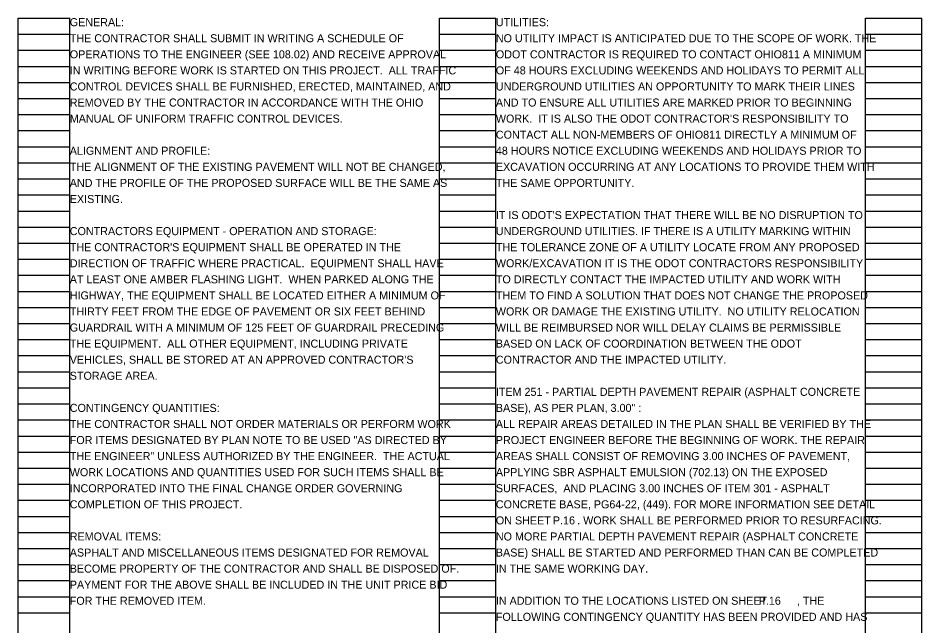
# Model space of a CAD drawing. Extents: x 28776.5 to 28808.5, y 9178.8 to 9230.7.
# Drawn here: x 28778.03 to 28793.77, y 9220.15 to 9230.74 of the extents above; entities that cross this region are included whole.
import ezdxf

# ---------------------------------------------------------------- set-up
doc = ezdxf.new("R2010")
doc.units = 0
doc.layers.add('SH_Data', color=7, linetype='Continuous')
doc.layers.add('SH_Text', color=7, linetype='Continuous')

msp = doc.modelspace()

# ---------------------------------------------------------------- linework, layer by layer
at = {"layer": 'SH_Data'}
for p, q in [((28778.029, 9210.582), (28778.029, 9230.742)), ((28778.029, 9230.742), (28778.929, 9230.742)), ((28778.929, 9210.582), (28778.929, 9230.742)), ((28785.369, 9210.582), (28785.369, 9230.742)), ((28785.369, 9230.742), (28786.349, 9230.742)), ((28786.349, 9210.582), (28786.349, 9230.742)), ((28792.789, 9210.582), (28792.789, 9230.742)), ((28792.789, 9230.742), (28793.769, 9230.742)), ((28793.769, 9210.582), (28793.769, 9230.742)), ((28778.029, 9230.462), (28778.929, 9230.462)), ((28785.369, 9230.462), (28786.349, 9230.462)), ((28792.789, 9230.462), (28793.769, 9230.462)), ((28778.029, 9230.182), (28778.929, 9230.182)), ((28785.369, 9230.182), (28786.349, 9230.182)), ((28792.789, 9230.182), (28793.769, 9230.182)), ((28778.029, 9229.902), (28778.929, 9229.902)), ((28785.369, 9229.902), (28786.349, 9229.902)), ((28792.789, 9229.902), (28793.769, 9229.902)), ((28778.029, 9229.622), (28778.929, 9229.622)), ((28785.369, 9229.622), (28786.349, 9229.622)), ((28792.789, 9229.622), (28793.769, 9229.622)), ((28778.029, 9229.342), (28778.929, 9229.342)), ((28785.369, 9229.342), (28786.349, 9229.342)), ((28792.789, 9229.342), (28793.769, 9229.342)), ((28778.029, 9229.062), (28778.929, 9229.062)), ((28785.369, 9229.062), (28786.349, 9229.062)), ((28792.789, 9229.062), (28793.769, 9229.062)), ((28778.029, 9228.782), (28778.929, 9228.782)), ((28785.369, 9228.782), (28786.349, 9228.782)), ((28792.789, 9228.782), (28793.769, 9228.782)), ((28778.029, 9228.502), (28778.929, 9228.502)), ((28785.369, 9228.502), (28786.349, 9228.502)), ((28792.789, 9228.502), (28793.769, 9228.502)), ((28778.029, 9228.222), (28778.929, 9228.222)), ((28785.369, 9228.222), (28786.349, 9228.222)), ((28792.789, 9228.222), (28793.769, 9228.222)), ((28778.029, 9227.942), (28778.929, 9227.942)), ((28785.369, 9227.942), (28786.349, 9227.942)), ((28792.789, 9227.942), (28793.769, 9227.942)), ((28778.029, 9227.662), (28778.929, 9227.662)), ((28785.369, 9227.662), (28786.349, 9227.662)), ((28792.789, 9227.662), (28793.769, 9227.662)), ((28778.029, 9227.382), (28778.929, 9227.382)), ((28785.369, 9227.382), (28786.349, 9227.382)), ((28792.789, 9227.382), (28793.769, 9227.382)), ((28778.029, 9227.102), (28778.929, 9227.102)), ((28785.369, 9227.102), (28786.349, 9227.102)), ((28792.789, 9227.102), (28793.769, 9227.102)), ((28778.029, 9226.822), (28778.929, 9226.822)), ((28785.369, 9226.822), (28786.349, 9226.822)), ((28792.789, 9226.822), (28793.769, 9226.822)), ((28778.029, 9226.542), (28778.929, 9226.542)), ((28785.369, 9226.542), (28786.349, 9226.542)), ((28792.789, 9226.542), (28793.769, 9226.542)), ((28778.029, 9226.262), (28778.929, 9226.262)), ((28785.369, 9226.262), (28786.349, 9226.262)), ((28792.789, 9226.262), (28793.769, 9226.262)), ((28778.029, 9225.982), (28778.929, 9225.982)), ((28785.369, 9225.982), (28786.349, 9225.982)), ((28792.789, 9225.982), (28793.769, 9225.982)), ((28778.029, 9225.702), (28778.929, 9225.702)), ((28785.369, 9225.702), (28786.349, 9225.702)), ((28792.789, 9225.702), (28793.769, 9225.702)), ((28778.029, 9225.422), (28778.929, 9225.422)), ((28785.369, 9225.422), (28786.349, 9225.422)), ((28792.789, 9225.422), (28793.769, 9225.422)), ((28778.029, 9225.142), (28778.929, 9225.142)), ((28785.369, 9225.142), (28786.349, 9225.142)), ((28792.789, 9225.142), (28793.769, 9225.142)), ((28778.029, 9224.862), (28778.929, 9224.862)), ((28785.369, 9224.862), (28786.349, 9224.862)), ((28792.789, 9224.862), (28793.769, 9224.862)), ((28778.029, 9224.582), (28778.929, 9224.582)), ((28785.369, 9224.582), (28786.349, 9224.582)), ((28792.789, 9224.582), (28793.769, 9224.582)), ((28778.029, 9224.302), (28778.929, 9224.302)), ((28785.369, 9224.302), (28786.349, 9224.302)), ((28792.789, 9224.302), (28793.769, 9224.302)), ((28778.029, 9224.022), (28778.929, 9224.022)), ((28785.369, 9224.022), (28786.349, 9224.022)), ((28792.789, 9224.022), (28793.769, 9224.022)), ((28778.029, 9223.742), (28778.929, 9223.742)), ((28785.369, 9223.742), (28786.349, 9223.742)), ((28792.789, 9223.742), (28793.769, 9223.742)), ((28778.029, 9223.462), (28778.929, 9223.462)), ((28785.369, 9223.462), (28786.349, 9223.462)), ((28792.789, 9223.462), (28793.769, 9223.462)), ((28778.029, 9223.182), (28778.929, 9223.182)), ((28785.369, 9223.182), (28786.349, 9223.182)), ((28792.789, 9223.182), (28793.769, 9223.182)), ((28778.029, 9222.902), (28778.929, 9222.902)), ((28785.369, 9222.902), (28786.349, 9222.902)), ((28792.789, 9222.902), (28793.769, 9222.902)), ((28778.029, 9222.622), (28778.929, 9222.622)), ((28785.369, 9222.622), (28786.349, 9222.622)), ((28792.789, 9222.622), (28793.769, 9222.622)), ((28778.029, 9222.342), (28778.929, 9222.342)), ((28785.369, 9222.342), (28786.349, 9222.342)), ((28792.789, 9222.342), (28793.769, 9222.342)), ((28778.029, 9222.062), (28778.929, 9222.062)), ((28785.369, 9222.062), (28786.349, 9222.062)), ((28792.789, 9222.062), (28793.769, 9222.062)), ((28778.029, 9221.782), (28778.929, 9221.782)), ((28785.369, 9221.782), (28786.349, 9221.782)), ((28792.789, 9221.782), (28793.769, 9221.782)), ((28778.029, 9221.502), (28778.929, 9221.502)), ((28785.369, 9221.502), (28786.349, 9221.502)), ((28792.789, 9221.502), (28793.769, 9221.502)), ((28778.029, 9221.222), (28778.929, 9221.222)), ((28785.369, 9221.222), (28786.349, 9221.222)), ((28792.789, 9221.222), (28793.769, 9221.222)), ((28778.029, 9220.942), (28778.929, 9220.942)), ((28785.369, 9220.942), (28786.349, 9220.942)), ((28792.789, 9220.942), (28793.769, 9220.942)), ((28778.029, 9220.662), (28778.929, 9220.662)), ((28785.369, 9220.662), (28786.349, 9220.662)), ((28792.789, 9220.662), (28793.769, 9220.662)), ((28778.029, 9220.382), (28778.929, 9220.382)), ((28785.369, 9220.382), (28786.349, 9220.382)), ((28792.789, 9220.382), (28793.769, 9220.382))]:
    msp.add_line(p, q, dxfattribs=at)

# ---------------------------------------------------------------- texts
at = {"layer": 'SH_Text'}
for s, p in [('GENERAL:', (28778.929, 9230.602)), ('UTILITIES:', (28786.349, 9230.602)), ('THE CONTRACTOR SHALL SUBMIT IN WRITING A SCHEDULE OF ', (28778.929, 9230.322)), ('NO UTILITY IMPACT IS ANTICIPATED DUE TO THE SCOPE OF WORK. THE ', (28786.349, 9230.322)), ('OPERATIONS TO THE ENGINEER (SEE 108.02) AND RECEIVE APPROVAL ', (28778.929, 9230.042)), ('ODOT CONTRACTOR IS REQUIRED TO CONTACT OHIO811 A MINIMUM ', (28786.349, 9230.042)), ('IN WRITING BEFORE WORK IS STARTED ON THIS PROJECT.  ALL TRAFFIC ', (28778.929, 9229.762)), ('OF 48 HOURS EXCLUDING WEEKENDS AND HOLIDAYS TO PERMIT ALL ', (28786.349, 9229.762)), ('CONTROL DEVICES SHALL BE FURNISHED, ERECTED, MAINTAINED, AND ', (28778.929, 9229.482)), ('UNDERGROUND UTILITIES AN OPPORTUNITY TO MARK THEIR LINES ', (28786.349, 9229.482)), ('REMOVED BY THE CONTRACTOR IN ACCORDANCE WITH THE OHIO ', (28778.929, 9229.202)), ('AND TO ENSURE ALL UTILITIES ARE MARKED PRIOR TO BEGINNING ', (28786.349, 9229.202)), ('MANUAL OF UNIFORM TRAFFIC CONTROL DEVICES.', (28778.929, 9228.922)), ("WORK.  IT IS ALSO THE ODOT CONTRACTOR'S RESPONSIBILITY TO ", (28786.349, 9228.922)), ('CONTACT ALL NON-MEMBERS OF OHIO811 DIRECTLY A MINIMUM OF ', (28786.349, 9228.642)), ('ALIGNMENT AND PROFILE:', (28778.929, 9228.362)), ('48 HOURS NOTICE EXCLUDING WEEKENDS AND HOLIDAYS PRIOR TO ', (28786.349, 9228.362)), ('THE ALIGNMENT OF THE EXISTING PAVEMENT WILL NOT BE CHANGED, ', (28778.929, 9228.082)), ('EXCAVATION OCCURRING AT ANY LOCATIONS TO PROVIDE THEM WITH ', (28786.349, 9228.082)), ('AND THE PROFILE OF THE PROPOSED SURFACE WILL BE THE SAME AS ', (28778.929, 9227.802)), ('THE SAME OPPORTUNITY.', (28786.349, 9227.802)), ('EXISTING. ', (28778.929, 9227.522)), ("IT IS ODOT'S EXPECTATION THAT THERE WILL BE NO DISRUPTION TO ", (28786.349, 9227.242)), ('CONTRACTORS EQUIPMENT - OPERATION AND STORAGE:', (28778.929, 9226.962)), ('UNDERGROUND UTILITIES. IF THERE IS A UTILITY MARKING WITHIN ', (28786.349, 9226.962)), ("THE CONTRACTOR'S EQUIPMENT SHALL BE OPERATED IN THE ", (28778.929, 9226.682)), ('THE TOLERANCE ZONE OF A UTILITY LOCATE FROM ANY PROPOSED ', (28786.349, 9226.682)), ('DIRECTION OF TRAFFIC WHERE PRACTICAL.  EQUIPMENT SHALL HAVE ', (28778.929, 9226.402)), ('WORK/EXCAVATION IT IS THE ODOT CONTRACTORS RESPONSIBILITY ', (28786.349, 9226.402)), ('AT LEAST ONE AMBER FLASHING LIGHT.  WHEN PARKED ALONG THE ', (28778.929, 9226.122)), ('TO DIRECTLY CONTACT THE IMPACTED UTILITY AND WORK WITH ', (28786.349, 9226.122)), ('HIGHWAY, THE EQUIPMENT SHALL BE LOCATED EITHER A MINIMUM OF ', (28778.929, 9225.842)), ('THEM TO FIND A SOLUTION THAT DOES NOT CHANGE THE PROPOSED ', (28786.349, 9225.842)), ('THIRTY FEET FROM THE EDGE OF PAVEMENT OR SIX FEET BEHIND ', (28778.929, 9225.562)), ('WORK OR DAMAGE THE EXISTING UTILITY.  NO UTILITY RELOCATION ', (28786.349, 9225.562)), ('GUARDRAIL WITH A MINIMUM OF 125 FEET OF GUARDRAIL PRECEDING ', (28778.929, 9225.282)), ('WILL BE REIMBURSED NOR WILL DELAY CLAIMS BE PERMISSIBLE ', (28786.349, 9225.282)), ('THE EQUIPMENT.  ALL OTHER EQUIPMENT, INCLUDING PRIVATE ', (28778.929, 9225.002)), ('BASED ON LACK OF COORDINATION BETWEEN THE ODOT ', (28786.349, 9225.002)), ("VEHICLES, SHALL BE STORED AT AN APPROVED CONTRACTOR'S ", (28778.929, 9224.722)), ('CONTRACTOR AND THE IMPACTED UTILITY.', (28786.349, 9224.722)), ('STORAGE AREA.', (28778.929, 9224.442)), ('ITEM 251 - PARTIAL DEPTH PAVEMENT REPAIR (ASPHALT CONCRETE ', (28786.349, 9224.162)), ('CONTINGENCY QUANTITIES:', (28778.929, 9223.882)), ('BASE), AS PER PLAN, 3.00" :', (28786.349, 9223.882)), ('THE CONTRACTOR SHALL NOT ORDER MATERIALS OR PERFORM WORK ', (28778.929, 9223.602)), ('ALL REPAIR AREAS DETAILED IN THE PLAN SHALL BE VERIFIED BY THE ', (28786.349, 9223.602)), ('FOR ITEMS DESIGNATED BY PLAN NOTE TO BE USED "AS DIRECTED BY ', (28778.929, 9223.322)), ('PROJECT ENGINEER BEFORE THE BEGINNING OF WORK. THE REPAIR ', (28786.349, 9223.322)), ('THE ENGINEER" UNLESS AUTHORIZED BY THE ENGINEER.  THE ACTUAL ', (28778.929, 9223.042)), ('AREAS SHALL CONSIST OF REMOVING 3.00 INCHES OF PAVEMENT, ', (28786.349, 9223.042)), ('WORK LOCATIONS AND QUANTITIES USED FOR SUCH ITEMS SHALL BE ', (28778.929, 9222.762)), ('APPLYING SBR ASPHALT EMULSION (702.13) ON THE EXPOSED ', (28786.349, 9222.762)), ('INCORPORATED INTO THE FINAL CHANGE ORDER GOVERNING ', (28778.929, 9222.482)), ('SURFACES,  AND PLACING 3.00 INCHES OF ITEM 301 - ASPHALT ', (28786.349, 9222.482)), ('COMPLETION OF THIS PROJECT.', (28778.929, 9222.202)), ('CONCRETE BASE, PG64-22, (449). FOR MORE INFORMATION SEE DETAIL ', (28786.349, 9222.202)), ('ON SHEET', (28786.349, 9221.922)), ('P.16', (28787.342, 9221.922)), ('          . WORK SHALL BE PERFORMED PRIOR TO RESURFACING. ', (28787.245, 9221.922)), ('REMOVAL ITEMS:', (28778.929, 9221.642)), ('NO MORE PARTIAL DEPTH PAVEMENT REPAIR (ASPHALT CONCRETE ', (28786.349, 9221.642)), ('ASPHALT AND MISCELLANEOUS ITEMS DESIGNATED FOR REMOVAL ', (28778.929, 9221.362)), ('BASE) SHALL BE STARTED AND PERFORMED THAN CAN BE COMPLETED ', (28786.349, 9221.362)), ('BECOME PROPERTY OF THE CONTRACTOR AND SHALL BE DISPOSED OF. ', (28778.929, 9221.082)), ('IN THE SAME WORKING DAY.', (28786.349, 9221.082)), ('PAYMENT FOR THE ABOVE SHALL BE INCLUDED IN THE UNIT PRICE BID ', (28778.929, 9220.802)), ('FOR THE REMOVED ITEM.', (28778.929, 9220.522)), ('IN ADDITION TO THE LOCATIONS LISTED ON SHEET          , THE ', (28786.349, 9220.522)), ('P.16', (28790.926, 9220.522)), ('FOLLOWING CONTINGENCY QUANTITY HAS BEEN PROVIDED AND HAS ', (28786.349, 9220.242))]:
    msp.add_text(s, height=0.14, dxfattribs=at).set_placement(p)

doc.saveas('drawing.dxf')
